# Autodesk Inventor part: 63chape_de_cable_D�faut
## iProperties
Created: 2011-01
Part Number: 63chape_de_cable_D�faut
Document SubType Name: Modeling
Designer: eric
Density: 1 g/cm^3
Mass: 0.619745 g
Surface Area: 14.4697 cm^2
Volume: 0.619745 cm^3
Author: eric
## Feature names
1. Base1
